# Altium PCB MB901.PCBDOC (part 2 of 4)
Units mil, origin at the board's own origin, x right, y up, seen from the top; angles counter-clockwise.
Board outline 4505 x 7005 mil, 4 copper layers (TopLayer, GND, VCC, BottomLayer); 333 components, 312 nets, 1570 pads, 794 vias.
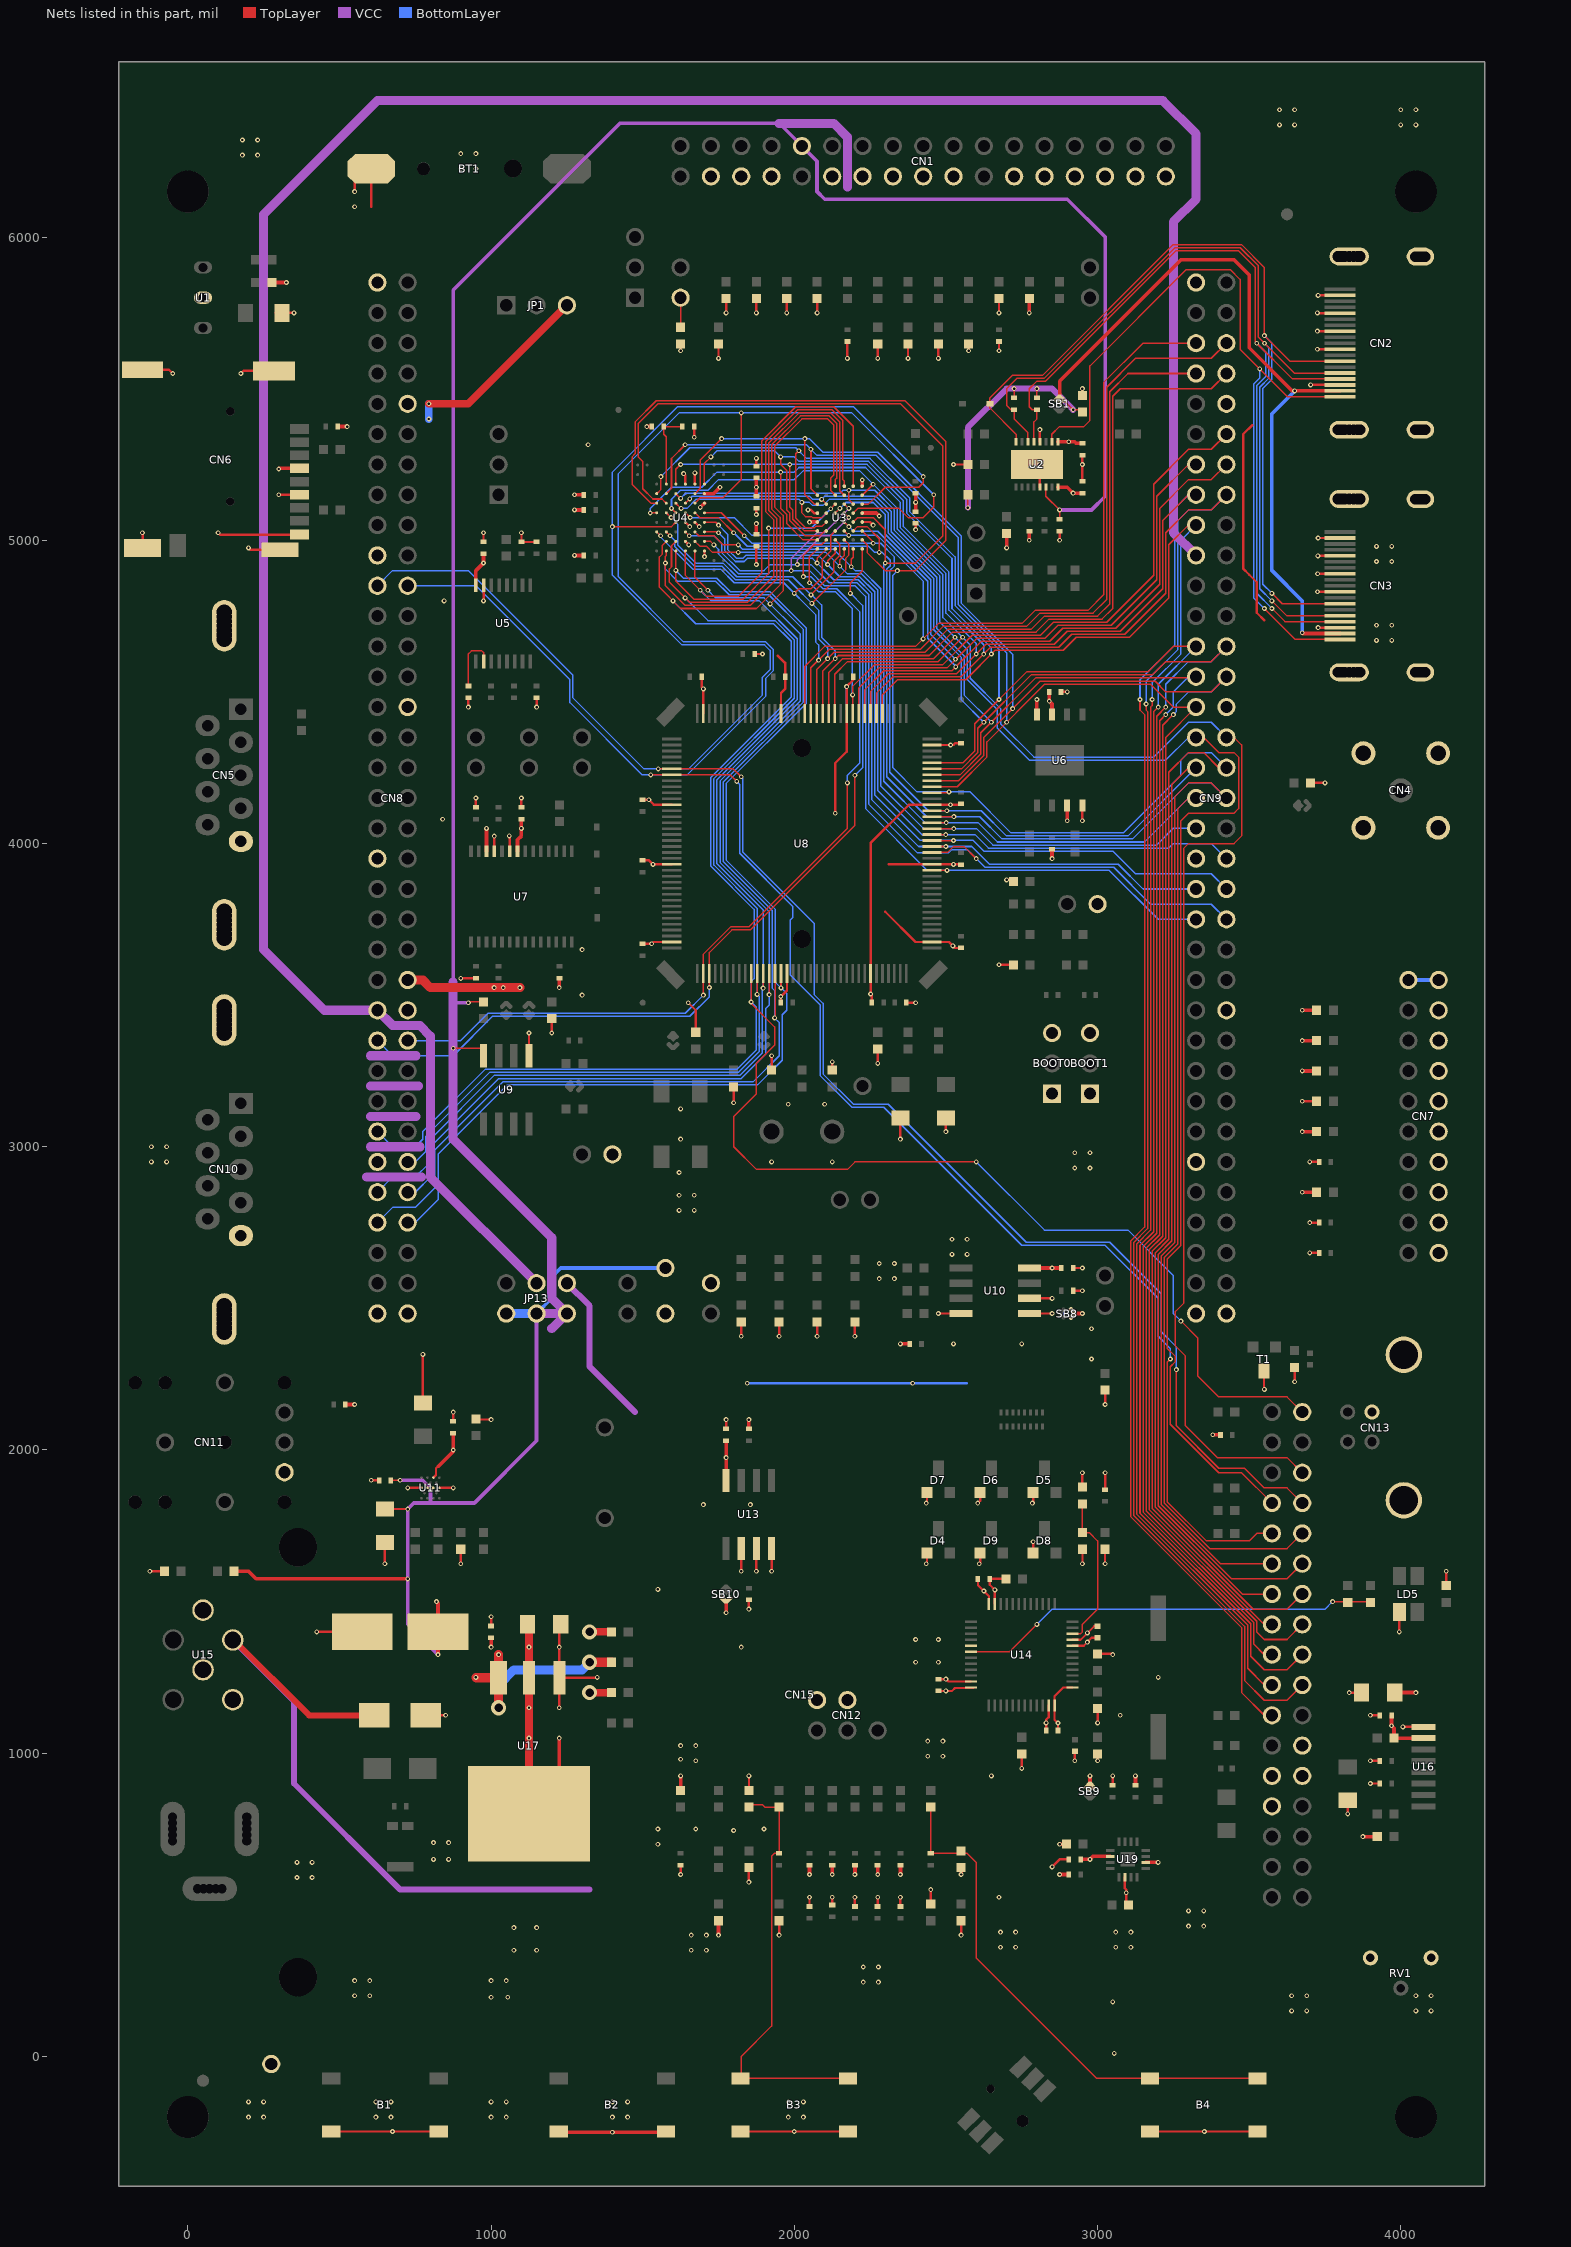
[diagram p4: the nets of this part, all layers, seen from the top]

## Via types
v1: diameter 16, hole 8, TopLayer to BottomLayer, tented both sides, 671 vias
v2: diameter 16, hole 8, TopLayer to BottomLayer, 117 vias
v3: diameter 50, hole 28, TopLayer to BottomLayer, 5 vias
v4: diameter 50, hole 28, TopLayer to BottomLayer, tented both sides, 1 vias

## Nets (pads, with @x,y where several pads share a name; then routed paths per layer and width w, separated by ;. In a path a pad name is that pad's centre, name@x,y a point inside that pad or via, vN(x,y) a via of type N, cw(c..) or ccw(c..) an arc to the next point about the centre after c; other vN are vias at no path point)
+3V3: B2.1 B2.4 BOOT0.1 BOOT1.1 C16.1 C17.2 C18.1 C19.1 C21.1 C22.2 C23.1 C31.2 C34.2 C56.2 C59.2 C61.1 C67.2 C68.2 C69.1 C70.1 C72.2 C74.1 C77.1 C78.1 C83.1 CN1.28 CN6.4 CN7.1 CN7.2 CN8.48 CN8.69 CN9.69 CN12.4 CN15.24 CN15.25 JP1.3 JP10.2 R2.2 R10.2 R15.2 R17.1 R21.2 R23.2 R25.1 R27.1 R29.1 R31.1 R32.1 R34.1 R45.2 R50.1 R54.2 R57.2 R63.2 R67.2 R69.2 R80.2 R82.1 R83.1 R84.2 R86.1 R87.2 R91.1 R96.1 R102.2 R111.2 R112.1 R114.2 R115.1 R117.2 R118.1 R119.2 R120.2 R121.2 R122.2 R123.2 R124.1 R131.2 R137.1 RV1.1 SB8.1 SB9.2 SB10.1 T1.3 TP5.1 U2.8 U2.9 U3.A6 U3.D6 U3.E1 U4.B6 U4.C6 U5.16 U6.3 U6.7 U6.8 U7.22 U7.26 U10.8 U11.E3 U13.8 U14.1 U14.9 U14.24 U14.36 U14.48 U16.7 U17.2 U19.6 U19.14 | length 6378.7
  TopLayer w7: U11.E3@809.84,1909.09 810,1909.09 818.53,1917.62 818.53,1939.53 826,1947 ; R83.1@952.5,2100 v1(1000,2100) ; v2(1100,5025) R31.1@1100,4994.5 R27.1@1150,4994.5 ; R102.2@1850,877.5 v2(1850,925) ; C74.1@2475,1205.5 2520.5,1205.5 2530,1215 U14.36@2590,1215 ; C67.2@2605.5,1575 2605.5,1554.5 2641.73,1518.27 U14.24@2641.73,1492.32 ; C68.2@2869.5,1075 v2(2869.5,1099.5) 2858.27,1110.73 2858.27,1188.27 2886.73,1216.73 U14.1@2917.32,1216.73 ; U14.9@2917.32,1374.21 2944.21,1374.21 2989,1419 C72.2@3000,1419 ; v2(2950,1625) R91.1@2950,1672.5 ; v2(3025,1625) R87.2@3025,1672.5 ; T1.3@3549.5,2260 3549.5,2200.5 v2(3550,2200) ; R131.2@4150,1552.5 v2(4150,1600)
  TopLayer w12: R2.2@277.5,5850 v1(325,5850) ; v1(300,5235) 302.01,5237.01 CN6.4@368.35,5237.01 ; R15.2@494.5,5375 v1(525,5375) ; R82.1@519.5,2150 v1(550,2150) ; 826.5,1946.5 875,1995 C61.1@875,2055.5 ; U5.16@950,4851.97 950,4900 v1(975,4925) C23.1@975,4955.5 ; U7.26@984.84,3974.61 v1(984.84,4049.84) ; v1(1000,1350) C70.1@1000,1380.5 ; U7.22@1087.2,3974.61 1087.2,4012.2 1100,4025 C34.2@1100,4080.5 ; U17.2@1225,880 v2(1225,1050) ; v1(1225,3525) R50.1@1225,3555.5 ; B2.1@1225.33,-250 B2.4@1580,-250 ; v1(1275,4950) R32.1@1305.5,4950 ; v1(1275,5100) R25.1@1305.5,5100 ; v1(1275,5150) R21.2@1305.5,5150 ; v1(1513.5,5375) R17.1@1530.5,5375 ; R111.2@1625,877.5 v1(1625,925) ; v1(1690,5108.5) U4.C6@1703.74,5122.24 ; U4.B6@1703.74,5153.74 1733.74,5153.74 v1(1755,5175) ; v1(1750,400) R124.1@1750,447.5 ; v1(1775,1463) SB10.1@1775,1500 ; U13.8@1775,1900 C59.2@1775,2030.5 ; R86.1@1850,2069.5 v1(1850,2100) ; C21.1@1875,5019.5 v1(1875,5055) ; C22.2@1875,5144.5 C17.2@1875,5205.5 ; v1(2050,600) R117.2@2050,630.5 ; v1(2050,5060) 2050.24,5060.24 U3.E1@2076.18,5060.24 ; v1(2125,600) R118.1@2125,630.5 ; v1(2200,600) R119.2@2200,630.5 ; U3.D6@2223.82,5089.76 2270.24,5089.76 v1(2280,5080) ; U3.A6@2223.82,5178.35 v2(2223.82,5198.82) ; v1(2275,600) R120.2@2275,630.5 ; v1(2350,600) R121.2@2350,630.5 ; v1(2350,2350) R80.2@2380.5,2350 ; C18.1@2400,5094.5 R23.2@2400,5155.5 ; v1(2550,600) R122.2@2550,630.5 ; v1(2700,4975) R29.1@2700,5022.5 ; U10.8@2775,2600 C56.2@2880.5,2600 ; v1(2775,5000) R34.1@2775,5030.5 ; v1(2775,5750) R10.2@2775,5797.5 ; U6.8@2800,4425 v1(2800,4475) ; C31.2@2840.5,4500 v1(2840.5,4469.5) 2850,4460 U6.7@2850,4425 ; v1(2850,3950) R45.2@2850,3980.5 ; U2.8@2868.9,5175.2 2899.8,5175.2 v1(2919.5,5155.5) C19.1@2950,5155.5 ; U2.9@2868.9,5324.8 2925,5324.8 2930.3,5319.5 C16.1@2950,5319.5 ; v1(2875,600) R123.2@2905.5,600 ; v1(2875,700) R112.1@2905.5,700 ; v1(2900,4075) U6.3@2900,4125 ; SB8.1@2920,2450 v1(2950,2450) ; C83.1@2944.5,650 v1(2975,650) 2984.84,659.84 U19.6@3041.26,659.84 ; SB9.2@2975,888 v1(2975,925) ; R114.2@3125,894.5 v1(3125,925) ; U19.14@3158.74,640.16 v1(3199.84,640.16) ; v1(3380,2050) R84.2@3405.5,2050 ; v1(3675,2850) R69.2@3722.5,2850 ; v1(3675,3050) R67.2@3722.5,3050 ; v1(3675,3250) R63.2@3722.5,3250 ; v1(3675,3350) R57.2@3722.5,3350 ; v1(3675,3450) R54.2@3722.5,3450 ; v1(3875,725) R115.1@3922.5,725 ; C78.1@3969.5,1125 v1(3969.5,1090.5) 3977.5,1082.5 R96.1@3977.5,1050 3978.09,1049.41 U16.7@4075,1049.41 ; C77.1@3980,1200 v1(4050,1200)
  TopLayer w25: v2(795,5450) 925,5450 JP1.3@1250,5775 ; U17.2@1125,795 C69.1@1125,1430 ; v3(1325,1200) R137.1@1397.5,1200
  TopLayer w30: CN8.48@725,3550 775,3550 800,3525 v1(1095,3525)
  BottomLayer w12: CN7.1@4025,3550 CN7.2@4125,3550
  BottomLayer w25: v2(795,5400) v2(795,5450)
  other v1: 1400,-250 1775,1975 875,2000 2850,2600 1010,3525 1040,3525 1100,4050 2400,5125 1875,5175 2905,5324.8
  other v2: 1125,1050 1125,1150 2500,1205.5 1125,1350 2966.64,1396.64 2625,1535
+5V: C20.1 C60.1 C62.1 C71.1 CN1.25 JP13.1 JP13.3 JP13.5 R55.2 R92.2 R136.1 TP4.1 U2.6 U9.8 U11.C3 U11.C5 U17.3 | length 11892.9
  TopLayer w5: C60.1@669.5,1900 v1(700,1900) ; U11.C5@790.16,1875 U11.C3@809.84,1875 ; v1(875,3325) U9.8@975,3325 ; v1(925,3475) 927.5,3477.5 R55.2@975,3477.5 ; U2.6@2829.53,5175.2 2829.53,5145.47 v1(2875,5100) C20.1@2875,5069.5
  TopLayer w7: C62.1@650,1805 v1(725,1805)
  TopLayer w12: R92.2@152.5,1600 200,1600 225,1575 v1(725,1575) ; v2(820,1500) 825,1495 v1(825,1325)
  TopLayer w30: v1(950,1250) 951.18,1248.82 U17.3@1025,1248.82 ; v4(1025,1150) v1(1025,1325) ; v3(1325,1300) R136.1@1397.5,1300
  VCC w12: v1(700,1900) 775,1900 v1(800,1875) 800,1825 ; v1(825,1325) 725,1425 v1(725,1805) 745,1825 945,1825 1150,2030 JP13.3@1150,2450 ; 875,3475 v1(925,3475) ; 875,3542.39 875,5825 1425,6375 1950,6375 2075,6250 2075,6150 2100,6125 2900,6125 3025,6000 3025,5145 2980,5100 v1(2875,5100)
  VCC w30: 875,3542.39 875,3025 1200,2700 1200,2500 JP13.5@1250,2450 ; JP13.3@1150,2450 JP13.5@1250,2450 ; 1200,2400 JP13.5@1250,2450 ; 1950,6375 2130,6375 2175,6330 2175,6165
  BottomLayer w12: JP13.3@1150,2450 1200,2500 1200,2570 1230,2600 TP4.1@1575,2600
  BottomLayer w30: v4@1025,1170 1025,1225 1075,1275 1300,1275 v3(1325,1300) ; JP13.1@1050,2450 JP13.3@1150,2450
A0: CN8.57 CN15.2 U3.A3 U4.G2 U8.10 | length 8019.9
  TopLayer w5: U4.G2@1577.76,4996.26 1565,4983.5 1565,4955 1555,4945 1555,4845 1625,4775 1875,4775 1952.83,4852.83 1952.83,5075.45 1925,5103.28 1925,5315 2020,5410 2115,5410 2140,5385 2140,5204.76 2135.24,5200 U3.A3@2135.24,5178.35 ; U8.10@1857.68,3570.87 1857.68,3472.32 1935,3395 1935,3335 1875,3275 1875,3175 1800,3100 1800,3000 1875,2925 2175,2925 2200,2950 v2(2600,2950) ; v1(3275,2425) 3330,2370 3330,2245 3400,2175 3625,2175 CN15.2@3675,2125
  BottomLayer w5: CN8.57@625,3050 675,3000 750,3000 775,3025 775,3050 980,3255 1810,3255 1875,3320 1875,3460 v2(1857.68,3477.32) 1857.68,3545 1867.36,3554.68 1867.36,3782.64 1725,3925 1725,4218.43 1990,4483.43 1990,4666.72 1931.72,4725 1675,4725 v1(1600,4800) ; v2(2600,2950) 2825,2725 3100,2725 3250,2575 3250,2450 v1(3275,2425)
A1: CN8.60 U3.A4 U4.G3 U8.11 | length 4891.9
  TopLayer w5: U4.G3@1609.25,4996.26 1595,4982.01 1595,4912.24 1587.76,4905 1587.76,4862.24 1655,4795 1845,4795 1932.83,4882.83 1932.83,5067.17 1905,5095 1905,5325 2010,5430 2125,5430 2160,5395 2160,5200 2164.76,5195.24 U3.A4@2164.76,5178.35 ; v1(1877.36,3502.36) U8.11@1877.36,3570.87
  BottomLayer w5: CN8.60@725,2950 750,2950 785,2985 785,3035 995,3245 1815,3245 1885,3315 1885,3494.72 v1(1877.36,3502.36) 1877.36,3786.78 1735,3929.14 1735,4214.29 2000,4479.29 2000,4670.86 1935.86,4735 1715,4735 v1(1640,4810)
A2: CN8.61 U3.A5 U4.H4 U8.12 | length 4874.8
  TopLayer w5: U4.H4@1640.75,4964.76 1640.75,4884.25 1710,4815 1815,4815 1892.5,4892.5 1892.5,5327.5 2005,5440 2130,5440 2194.29,5375.71 U3.A5@2194.29,5178.35 ; v1(1897.05,3522.95) U8.12@1897.05,3570.87
  BottomLayer w5: CN8.61@625,2850 675,2900 750,2900 795,2945 795,3020 1010,3235 1820,3235 1895,3310 v1@1895,3520.9 ; v1(1690.03,4834.97) 1725,4800 1885,4800 2010,4675 2010,4475.15 1745,4210.15 1745,3933.28 1897.05,3781.24 v1(1897.05,3522.95)
A3: CN8.62 U3.B3 U4.H5 U8.13 | length 4606.8
  TopLayer w5: U4.H5@1672.24,4964.76 1672.24,4877.76 v1(1715,4835) ; v1(1916.73,3501.73) U8.13@1916.73,3570.87 ; v1(1920,4790) 1962.83,4832.83 1962.83,5082.17 1935,5110 1935,5310 2025,5400 2110,5400 2130,5380 2130,5215 2120,5205 2120,5164.06 U3.B3@2135.24,5148.82
  BottomLayer w5: CN8.62@725,2850 750,2850 805,2905 805,3005 1025,3225 1825,3225 1905,3305 1905,3455 1916.73,3466.73 1916.73,3775.69 1755,3937.43 1755,4206 2020,4471 2020,4690 1900,4810 1740,4810 v1(1715,4835)
A4: CN8.63 U3.B4 U4.H2 U8.14 | length 5462.1
  TopLayer w5: U4.H2@1577.76,4964.76 1577.76,4950 1575,4947.24 1575,4850 1640,4785 1855,4785 1942.83,4872.83 1942.83,5071.31 1915,5099.14 1915,5320 2015,5420 2120,5420 2150,5390 2150,5163.58 U3.B4@2164.76,5148.82 ; v1@1936.42,3426.42 U8.14@1936.42,3570.87
  BottomLayer w5: CN8.63@625,2750 675,2800 750,2800 815,2865 815,2990 1040,3215 1865,3215 1950,3300 1950,3410 v1(1935,3425) 1935,3515 1926.73,3523.27 1926.73,3779.84 1765,3941.57 1765,4201.86 2030,4466.86 2030,4705.86 1915.86,4820 1785.15,4820 1740.15,4865 1615,4865 1575,4905 v1(1575,4925)
A5: CN8.64 U3.C3 U4.H3 U8.15 | length 4593
  TopLayer w5: U4.H3@1610,4964.02 U4.H3@1609.25,4964.76 1609.25,4865.75 1670,4805 1830,4805 1915,4890 v2(1915,5040) ; v1(1956.1,3523.9) U8.15@1956.1,3570.87 ; v1@2120.94,5105 U3.C3@2135.24,5119.29
  BottomLayer w5: CN8.64@725,2750 750,2750 825,2825 825,2975 1055,3205 1880,3205 1960,3285 1960,3435 1975,3450 1975,3505 1936.73,3543.27 1936.73,3783.98 1775,3945.71 1775,4197.72 2040,4462.72 2040,4710 1920,4830 1789.29,4830 1744.29,4875 1635,4875 v1(1609.25,4900.75) ; v2(1915,5040) 2055.94,5040 v1(2120,5104.06)
A6: CN9.43 U3.C4 U4.G6 U8.50 | length 2932.6
  TopLayer w5: U4.G6@1703.74,4996.26 1723.74,4996.26 v1(1735,4985) ; U3.C4@2164.76,5119.29 v1@2179.06,5105 ; U8.50@2454.13,3911.42 v1(2503.58,3911.42)
  VCC w5: v1(1990,4900) 1990,4940 2075,5025 2100,5025 v1(2180,5105)
  BottomLayer w5: v1(1735,4985) 1750,4970 1750,4955 1815,4890 1915,4890 1925,4900 2050,4900 2100,4850 2200,4850 2235,4815 2235,4115 2438.58,3911.42 3038.58,3911.42 3200,3750 CN9.43@3325,3750
A7: CN9.44 U3.D4 U4.F4 U8.53 | length 3195.1
  TopLayer w5: U4.F4@1640.75,5027.76 v1(1653.5,5015) ; U3.D4@2164.76,5089.76 v1(2179.53,5075) ; U8.53@2454.13,3970.47 2505.47,3970.47 2525,3990 2560,3990 v1(2600,3950)
  VCC w5: v1(2010,4920) 2010,4935 2090,5015 2119.53,5015 v1(2179.53,5075)
  BottomLayer w5: v1(1653.5,5015) 1735,5015 1760,4990 1760,4960 1820,4900 1900,4900 1920,4920 2055,4920 2115,4860 2206.72,4860 2245,4821.72 2245,4130 2405,3970 2510,3970 2520,3980 2570,3980 2628.58,3921.42 3053.58,3921.42 3175,3800 3375,3800 CN9.44@3425,3750
A8: CN9.41 U3.H2 U4.F6 U8.54 | length 2644.4
  TopLayer w5: U4.F6@1703.74,5027.76 1747.24,5027.76 v1(1750,5025) ; v1(2075,4925) 2075,4940.94 U3.H2@2105.71,4971.65 ; U8.54@2454.13,3990.16 v1(2500,3990.16)
  BottomLayer w5: v1(1750,5025) 1770,5005 1770,4965.86 1805.86,4930 1835,4930 1845,4940 2060,4940 2130,4870 2210.86,4870 2255,4825.86 2255,4145 2409.84,3990.16 2584.84,3990.16 2643.58,3931.42 3068.58,3931.42 3150,3850 CN9.41@3325,3850
A9: CN9.42 U3.H3 U4.E6 U8.55 | length 2785
  TopLayer w5: U4.E6@1703.74,5059.25 1740.75,5059.25 v1(1750,5050) ; v1(2110,4920) 2110,4932.22 2135.24,4957.46 U3.H3@2135.24,4971.65 ; U8.55@2454.13,4009.84 v1@2524.84,4009.84
  BottomLayer w5: v1(1750,5050) 1780,5020 1780,4970 1810,4940 1830,4940 1840,4950 2080,4950 2150,4880 2215,4880 2265,4830 2265,4160 2415,4010 2590,4010 2625,3975 3050,3975 3125,3900 3375,3900 CN9.42@3425,3850
  other v1: 2525,4010
A10: CN9.40 U3.H4 U4.G5 U8.56 | length 2694.7
  TopLayer w5: U4.G5@1672.24,4996.26 1688.5,4980 1710,4980 1730,4960 v1(1815,4960) ; v1(2150,4914.14) 2150,4935.24 2164.76,4950 U3.H4@2164.76,4971.65 ; U8.56@2454.13,4029.53 v1(2499.53,4029.53)
  BottomLayer w5: v1(1815,4960) 2104.14,4960 2174.14,4890 2220.86,4890 2275,4835.86 2275,4175 2420.47,4029.53 2595.47,4029.53 2640,3985 3235,3985 3250,4000 3375,4000 CN9.40@3425,3950
A11: CN9.37 U3.H5 U4.F5 U8.57 | length 2617.6
  TopLayer w5: U4.F5@1672.24,5027.76 1685,5015 1735,5015 1765,4985 v1(1815,4985) ; v1(2187.59,4912.59) 2187.59,4937.59 2194.29,4944.29 U3.H5@2194.29,4971.65 ; U8.57@2454.13,4049.21 v1(2525.79,4049.21)
  BottomLayer w5: v1(1815,4985) 1830,4970 2130.17,4970 2200.17,4900 2225,4900 2285,4840 2285,4190 2425.79,4049.21 2600.79,4049.21 2655,3995 3195,3995 3250,4050 CN9.37@3325,4050
A12: CN9.8 U3.G3 U4.D2 U8.87 | length 3387.7
  TopLayer w5: U4.D2@1577.76,5090.75 v1(1593.5,5075) ; v1(2055,4820) 2130,4895 2130,4930 2150,4950 2150,4986.42 U3.G3@2135.24,5001.18 ; U8.87@2093.9,4429.13 2093.9,4568.9 2145,4620 2445,4620 2522.07,4697.07 2797.07,4697.07 2840,4740 3015,4740 3050,4775 3050,5475 3075,5500 3375,5500 CN9.8@3425,5550
  BottomLayer w5: v1(1593.5,5075) 1615,5053.5 1615,4985 1675,4925 1765,4925 1810,4880 1995,4880 v1(2055,4820) 2056.87,4820 2090,4786.87 2090,4680 2135,4635 v1(2135,4610)
A13: CN9.7 U3.G4 U4.F2 U8.88 | length 3269.1
  TopLayer w5: U4.F2@1577.76,5027.76 v1@1590,5015.51 ; v1(2057.98,4792.02) 2170,4904.03 2170,4941.09 2180,4951.09 2180,4985.94 U3.G4@2164.76,5001.18 ; U8.88@2074.21,4429.13 2074.21,4574.21 2130,4630 2430,4630 2507.07,4707.07 2782.07,4707.07 2825,4750 3000,4750 3040,4790 3040,5490 3100,5550 CN9.7@3325,5550
  BottomLayer w5: v1(1590,5015) 1605,5000 1605,4980 1670,4915 1760.86,4915 1805.86,4870 1980,4870 2080,4770 2080,4675 2110,4645 v1(2110,4610)
A14: CN9.6 U3.F3 U4.F1 U8.89 | length 3452.7
  TopLayer w5: U4.F1@1546.26,5027.76 v1(1559.02,5015) ; v1(2000,4825) 2015,4840 2055,4840 2092.78,4877.78 2092.78,4937.78 2120,4965 2120,5015.47 U3.F3@2135.24,5030.71 ; U8.89@2054.53,4429.13 2054.53,4579.53 2115,4640 2415,4640 2492.07,4717.07 2767.07,4717.07 2810,4760 2985,4760 3030,4805 3030,5505 3125,5600 3375,5600 CN9.6@3425,5650
  BottomLayer w5: v1(1559.02,5015) 1559.02,5010.98 1665,4905 1756.72,4905 1801.72,4860 1965,4860 2070,4755 2070,4665 2080,4655 v1(2080,4605)
A15: CN9.5 U3.F4 U4.D4 U8.90 | length 3386.4
  TopLayer w5: U4.D4@1640.75,5090.75 v1(1656.5,5075) ; U8.90@2034.84,4429.13 2034.84,4584.84 2100,4650 2400,4650 2477.07,4727.07 2752.07,4727.07 2795,4770 2970,4770 3020,4820 3020,5520 3150,5650 CN9.5@3325,5650 ; U3.F4@2164.76,5030.71 v1(2179.53,5015.94)
  BottomLayer w5: v1(1656.5,5075) 1801.72,5075 1860.77,5015.94 2274.06,5015.94 2424.7,4865.3 v1(2424.7,4674.7) v1@2425,4675
A16: CN9.14 U3.E4 U8.80 | length 2399.9
  TopLayer w5: U3.E4@2164.76,5060.24 v1(2180,5045) ; U8.80@2231.69,4429.13 2231.69,4506.69 2295,4570 2520,4570 v1@2532.5,4582.5 ; v1(2532.38,4582.62) 2532.62,4582.62 2617.07,4667.07 2842.07,4667.07 2885,4710 3060,4710 3205,4855 3205,5105 3300,5200 3375,5200 CN9.14@3425,5250
  BottomLayer w5: v1(2180,5045) 2195,5030 2275,5030 2440,4865 2440,4677.15 v1@2532.38,4584.77
A17: CN9.13 U3.D3 U8.81 | length 2430.9
  TopLayer w5: U3.D3@2135.24,5089.76 v1(2150.47,5105) ; U8.81@2212.01,4429.13 2212.01,4512.01 2280,4580 2505,4580 v1@2532.07,4607.07 ; v1@2532.56,4607.56 2602.07,4677.07 2827.07,4677.07 2870,4720 3045,4720 3195,4870 3195,5145 3300,5250 CN9.13@3325,5250
  BottomLayer w5: v1(2150.47,5105) 2170.03,5124.56 2260.44,5124.56 2300,5085 2300,5020 2450,4870 2450,4689.14 v1(2531.58,4607.56)
A18: CN9.12 U3.H1 U8.82 | length 2424
  TopLayer w5: v1(2050,4860) 2050,4945.47 U3.H1@2076.18,4971.65 ; U8.82@2192.32,4429.13 2192.32,4517.32 2265,4590 2490,4590 2587.07,4687.07 2812.07,4687.07 2855,4730 3030,4730 3185,4885 3185,5185 3300,5300 3375,5300 CN9.12@3425,5350
  BottomLayer w5: v1(2050,4860) 2080,4830 2135.86,4830 2191.17,4774.69 v1@2191.17,4491.16
  other v1: 2192.32,4490
A19: CN8.52 U3.G2 U8.2 | length 2950.1
  TopLayer w5: v1(1700.2,3500.2) 1700.2,3635.2 1790,3725 1850,3725 2175,4050 v1(2175,4200) ; v1(2030,4880) 2030,4950 2066,4986 2090.53,4986 U3.G2@2105.71,5001.18
  BottomLayer w5: CN8.52@725,3350 900,3350 990,3440 1640,3440 v1(1700.2,3500.2) ; v1(2030,4880) 2055,4880 2095,4840 2140,4840 2215,4765 2215,4265 2175,4225 v1(2175,4200)
A20: CN8.51 U3.H6 U8.3 | length 2950.6
  TopLayer w5: v1(1719.88,3525.12) 1719.88,3640.74 1794.14,3715 1855,3715 2200,4060 v1(2200,4225) ; v1(2185,4825) 2185,4860 2223.82,4898.82 U3.H6@2223.82,4971.65
  BottomLayer w5: CN8.51@625,3350 675,3300 875,3300 1005,3430 1655,3430 1719.88,3494.88 v1(1719.88,3525.12) ; v1(2185,4825) 2225,4785 2225,4250 v1(2200,4225)
AIN_1: R91.2 R93.1 U14.10 | length 512.3
  TopLayer w5: U14.10@2917.32,1393.9 2943.9,1393.9 2950,1400 2950,1425 3000,1475 3000,1700 2972.5,1727.5 R91.2@2950,1727.5 R93.1@2950,1822.5
D0: CN9.32 CN15.6 U3.B6 U4.D3 U8.85 | length 6194.9
  TopLayer w5: v1(1595,5105) U4.D3@1609.25,5090.75 ; U8.85@2133.27,4429.13 2133.27,4558.27 2175,4600 2475,4600 v1(2555,4680) ; U3.B6@2223.82,5148.82 v1(2260,5185) ; CN9.32@3425,4350 3450,4350 3475,4325 3475,4025 3450,4000 3300,4000 3285,3985 3285,2485 3257.01,2457.01 3257.01,2342.99 3290,2310 3290,2080 3395,1975 3625,1975 CN15.6@3675,1925
  BottomLayer w5: v1(1595,5105) 1595,5135 1625,5165 1715,5165 1750,5200 2000,5200 2030,5230 2215,5230 2340,5105 2340,5036.57 2490,4886.57 2490,4745 2580,4655 2580,4545 2680,4445 2680,4395 2790,4285 3185,4285 3300,4400 3375,4400 CN9.32@3425,4350
D1: CN9.31 CN15.7 U3.C5 U4.B3 U8.86 | length 6019.6
  TopLayer w5: U4.B3@1609.25,5153.74 v1(1625,5137.99) ; U8.86@2113.58,4429.13 2113.58,4563.58 2160,4610 2460,4610 v1(2530,4680) ; v1(2180,5165) 2180,5133.58 U3.C5@2194.29,5119.29 ; CN9.31@3325,4350 3350,4350 3400,4300 3450,4300 3465,4285 3465,4115 3450,4100 3300,4100 3275,4075 3275,2675 3230,2630 3230,2335 3257.01,2307.99 3257.01,2291.5 3240,2274.49 3240,2085 3400,1925 3475,1925 CN15.7@3575,1825
  BottomLayer w5: v1(1625,5137.99) 1642.01,5155 2150.44,5155 2160.44,5165 2265,5165 2330,5100 2330,5032.43 2480,4882.43 2480,4730 2570,4640 2570,4540.86 2670,4440.86 2670,4380 2775,4275 3225,4275 3300,4350 CN9.31@3325,4350
D2: CN8.21 CN15.8 U3.C6 U4.E3 U8.114 | length 8269.6
  TopLayer w5: v1(1400,5045) 1595,5045 U4.E3@1609.25,5059.25 ; v1(1551.06,4246.06) 1798.94,4246.06 v1(1825,4220) ; U3.C6@2223.82,5119.29 2244.29,5119.29 2300,5175 2410,5175 2425,5190 v1(2425,5210) ; v1(3260,2265) 3260,2080 3400,1940 3485,1940 3550,1875 3625,1875 CN15.8@3675,1825
  BottomLayer w5: CN8.21@625,4850 675,4900 925,4900 1270,4555 1270,4480 1503.94,4246.06 1651.06,4246.06 1895,4490 1895,4548.28 1920,4573.28 1920,4636.72 1901.72,4655 1630,4655 1400,4885 1400,5225 1615,5440 2195,5440 v1(2425,5210) ; v1(1825,4220) 1830,4215 1830,3971.72 2065,3736.72 2065,3502.43 2095,3472.43 2095,3240 2195,3140 2310,3140 2765,2685 3040,2685 3210,2515 3210,2390 3260,2340 v1(3260,2265)
D3: CN8.22 CN15.9 U3.D5 U4.C5 U8.115 | length 8587
  TopLayer w5: v1(1526.38,4226.38) 1788.62,4226.38 v1(1810,4205) ; U4.C5@1672.24,5122.24 1690,5140 1765,5140 1825,5200 v1(1825,5420) ; U3.D5@2194.29,5089.76 2209.53,5105 2345,5105 2375,5075 2425,5075 2460,5110 v1(2460,5150) ; v1(3240,2300) 3230,2290 3230,1828.85 3358.85,1700 3500,1700 3525,1725 CN15.9@3575,1725
  BottomLayer w5: CN8.22@725,4850 950,4850 1260,4540 1260,4465 1498.62,4226.38 1646.38,4226.38 1905,4485 1905,4544.14 1930,4569.14 1930,4640.86 1905.86,4665 1635,4665 1420,4880 1420,5220 1620,5420 2190,5420 v1(2460,5150) ; v1(1810,4205) 1820,4195 1820,3967.57 1995,3792.57 1995,3755.86 1986.1,3746.96 1986.1,3567.18 2085,3468.28 2085,3235 2190,3130 2295,3130 2750,2675 3025,2675 3200,2500 3200,2375 3240,2335 v1(3240,2300)
D4: CN9.35 CN15.10 U3.E5 U4.C2 U8.58 | length 7032.4
  TopLayer w5: U4.C2@1577.76,5122.24 1563.87,5136.13 1533.87,5136.13 1500,5170 1500,5260 1485,5275 1485,5385 1550,5450 2350,5450 2490,5310 2490,5015 2400,4925 v1(2300,4925) 2300,5035 2260,5075 2209.06,5075 U3.E5@2194.29,5060.24 ; U8.58@2454.13,4068.9 v1(2501.1,4068.9) ; CN9.35@3325,4150 3300,4150 3265,4115 3265,2680 3220,2635 3220,1824.71 3369.71,1675 3625,1675 CN15.10@3675,1725
  BottomLayer w5: v1(2300,4925) 2295,4920 2295,4205 2431.1,4068.9 2606.1,4068.9 2670,4005 3155,4005 3300,4150 CN9.35@3325,4150
D5: CN9.36 CN15.11 U3.F5 U4.D5 U8.59 | length 5963.6
  TopLayer w5: U4.D5@1672.24,5090.75 1687.99,5075 1750,5075 v1(1800,5025) ; U3.F5@2194.29,5030.71 2208.58,5045 2240,5045 2280,5005 v1(2280,4960) ; U8.59@2454.13,4088.58 v1(2526.42,4088.58) ; CN9.36@3425,4150 3375,4200 3300,4200 3255,4155 3255,2685 3210,2640 3210,1820.56 3405.56,1625 CN15.11@3575,1625
  BottomLayer w5: v1(1800,5025) 1845,4980 2245,4980 2265,4960 2290,4960 2316.18,4933.82 2316.18,4916.18 2305,4905 2305,4220 2436.42,4088.58 2611.42,4088.58 2685,4015 3115,4015 3300,4200 3375,4200 CN9.36@3425,4150
D5V: CN8.49 CN9.19 JP13.4 | length 9582.9
  VCC w30: 590,2900 770,2900 ; 602.09,3000 765,3000 ; 602.09,3100 752.43,3100 ; 602.09,3200 760,3200 ; 602.09,3300 752.75,3300 ; JP13.4@1150,2550 800,2900 800,3365 765,3400 675,3400 CN8.49@625,3450 450,3450 250,3650 250,6075 625,6450 3215,6450 3325,6340 3325,6125 3250,6050 3250,5025 CN9.19@3325,4950
D6: CN9.33 CN15.12 U3.F6 U4.D6 U8.60 | length 5793.6
  TopLayer w5: U4.D6@1703.74,5090.75 1759.25,5090.75 v1(1835,5015) ; U3.F6@2223.82,5030.71 2260,4994.53 v1(2260,4990) ; U8.60@2454.13,4108.27 v1(2503.27,4108.27) ; CN9.33@3325,4250 3300,4250 3245,4195 3245,2690 3200,2645 3200,1816.42 3441.42,1575 3625,1575 CN15.12@3675,1625
  BottomLayer w5: v1(1835,5015) 1860,4990 2285,4990 2330,4945 2330,4915 2315,4900 2315,4235 2441.73,4108.27 2616.73,4108.27 2700,4025 3100,4025 CN9.33@3325,4250
D7: CN9.34 CN15.13 U3.G6 U4.C1 U8.63 | length 7370.5
  TopLayer w5: U4.C1@1546.26,5122.24 1527.76,5122.24 1465,5185 1465,5275 1475,5285 1475,5390 1545,5460 2365,5460 2500,5325 2500,5000 2400,4900 2300,4900 2240,4960 2240,4985 U3.G6@2223.82,5001.18 ; U8.63@2454.13,4167.32 2507.32,4167.32 v1(2510,4170) ; CN9.34@3425,4250 3400,4250 3350,4300 3300,4300 3235,4235 3235,2695 3190,2650 3190,1812.28 3477.28,1525 CN15.13@3575,1525
  BottomLayer w5: v1(2340,4900) 2325,4885 2325,4250 2405,4170 2580,4170 2715,4035 3085,4035 3275,4225 3275,4275 3300,4300 3375,4300 CN9.34@3425,4250
D8: CN9.29 CN15.14 U3.B1 U4.B2 U8.64 | length 6451.5
  TopLayer w5: U4.B2@1577.76,5153.74 1595,5170.98 1595,5270 v1(1640,5315) ; v1@2055,5300 2055,5170 U3.B1@2076.18,5148.82 ; U8.64@2454.13,4187.01 2537.01,4187.01 2635,4285 2635,4335 2825,4525 3175,4525 3250,4450 CN9.29@3300,4450 ; CN9.29@3325,4450 3225,4350 3225,2700 3180,2655 3180,1808.14 3513.14,1475 3625,1475 CN15.14@3675,1525
  BottomLayer w5: v1(1640,5315) 2040,5315 2075,5280 2270,5280 2540,5010 2540,4789.14 2700,4629.14 v1(2700,4400)
  other v1: 2054.83,5300.17
D9: CN9.28 CN15.15 U3.C1 U4.B5 U8.65 | length 6654.4
  TopLayer w5: U4.B5@1672.24,5153.74 1690,5171.5 1690,5265 v1(1760.11,5335.11) ; v1(2035,5335.11) 2035,5150 2065.71,5119.29 U3.C1@2076.18,5119.29 ; U8.65@2454.13,4206.69 2541.69,4206.69 2625,4290 2625,4350 2810,4535 3190,4535 3225,4500 3375,4500 CN9.28@3425,4550 ; v1(3250,4425) 3215,4390 3215,2705 3170,2660 3170,1804 3549,1425 CN15.15@3575,1425
  BottomLayer w5: v1(1760.11,5335.11) 2049.89,5335.11 2095,5290 2275,5290 2550,5015 2550,4793.28 2720,4623.28 v1(2720,4445) ; v1(3250,4425) 3260,4435 3260,4460 3300,4500 3375,4500 CN9.28@3425,4550
D10: CN9.27 CN15.16 U3.C2 U4.C4 U8.66 | length 6189.1
  TopLayer w5: U4.C4@1640.75,5122.24 v1(1655,5136.5) ; v1(2090,5135) U3.C2@2105.71,5119.29 ; U8.66@2454.13,4226.38 2546.38,4226.38 2615,4295 2615,4365 2797.07,4547.07 CN9.27@3332.93,4547.07 ; v1(3225,4425) 3205,4405 3205,2710 3160,2665 3160,1799.85 3525,1434.85 3525,1400 3550,1375 3625,1375 CN15.16@3675,1425
  BottomLayer w5: v1(1655,5136.5) 1663.5,5145 2050,5145 2060,5135 v1(2090,5135) 2099.56,5144.56 2270.44,5144.56 2320,5095 2320,5028.28 2470,4878.28 2470,4709.14 2560,4619.14 2560,4490 v1(2650,4400) ; v1(3225,4425) 3250,4450 3250,4500 3300,4550 CN9.27@3325,4550
D11: CN9.26 CN15.17 U3.D2 U4.C3 U8.67 | length 6562.2
  TopLayer w5: U4.C3@1609.25,5122.24 v1(1626.5,5105) ; v1(2025,5125) 2025,5090 2036.74,5078.26 2056.74,5078.26 2060,5075 2090.94,5075 U3.D2@2105.71,5089.76 ; U8.67@2454.13,4246.06 2551.06,4246.06 2605,4300 2605,4380 2782.07,4557.07 3182.07,4557.07 3225,4600 3375,4600 CN9.26@3425,4650 ; v1(3225,4450) 3195,4420 3195,2715 3150,2670 3150,1795.71 3515,1430.71 3515,1360 3550,1325 CN15.17@3575,1325
  BottomLayer w5: v1(1626.5,5105) 1645.86,5105 1675.86,5135 2015,5135 v1(2025,5125) 2050,5125 2060,5115 2095,5115 2114.56,5134.56 2265.44,5134.56 2310,5090 2310,5024.14 2460,4874.14 2460,4705 2550,4615 2550,4475 v1(2625,4400) ; v1(3225,4450) 3225,4525 3300,4600 3375,4600 CN9.26@3425,4650
D12: CN9.25 CN15.18 U3.E2 U4.B1 U8.68 | length 6974.9
  TopLayer w5: U4.B1@1546.26,5153.74 1560,5167.48 v1(1560,5210) ; v1(2015,5295) 2005,5285 2005,5073.28 2037.58,5040.71 2065.71,5040.71 2071.74,5046.74 2092.21,5046.74 U3.E2@2105.71,5060.24 ; U8.68@2454.13,4265.75 2555.75,4265.75 2595,4305 2595,4395 2767.07,4567.07 3167.07,4567.07 3250,4650 CN9.25@3325,4650 ; v1(3200,4450) 3185,4435 3185,2720 3140,2675 3140,1791.57 3505,1426.57 3505,1320 3550,1275 3625,1275 CN15.18@3675,1325
  BottomLayer w5: v1(1560,5210) 1655,5305 2005,5305 2040,5270 2250,5270 2380,5140 2380,5095 2530,4945 2530,4785 2675,4640 v1(2675,4475) ; v1(3200,4450) 3200,4525 CN9.25@3325,4650
D13: CN9.17 CN15.19 U3.F2 U4.A6 U8.77 | length 7349.2
  TopLayer w5: U4.A6@1703.74,5185.24 1703.74,5253.74 v1(1725,5275) ; v1(1955,5275) 1955,5250 1975,5230 1975,5100 1985,5090 1985,5065 2035,5015 2085,5015 2100.71,5030.71 U3.F2@2105.71,5030.71 ; U8.77@2290.75,4429.13 2290.75,4490.75 2340,4540 2565,4540 2662.07,4637.07 2887.07,4637.07 2930,4680 3105,4680 3235,4810 3235,4985 3300,5050 CN9.17@3325,5050 ; v1(3180,4475) 3180,4455 3175,4450 3175,2725 3130,2680 3130,1787.43 3495,1422.43 3495,1280 3550,1225 CN15.19@3575,1225
  BottomLayer w5: v1(1725,5275) 1745,5295 1935,5295 v1(1955,5275) 2000,5275 2015,5260 2245,5260 2370,5135 2370,5090 2520,4940 2520,4775 2650,4645 v1(2650,4625) ; v1(3180,4475) 3180,4530 3275,4625 3275,5000 CN9.17@3325,5050
D14: CN9.16 CN15.20 U3.F1 U4.A3 U8.78 | length 7835.1
  TopLayer w5: U4.A3@1609.25,5185.24 1609.25,5234.25 v1(1625,5250) ; v1(1985,5250) 1985,5110 1995,5100 1995,5069.14 2033.43,5030.71 U3.F1@2076.18,5030.71 ; U8.78@2271.06,4429.13 2271.06,4496.06 2325,4550 2550,4550 2647.07,4647.07 2872.07,4647.07 2915,4690 3090,4690 3225,4825 3225,5025 3300,5100 3375,5100 CN9.16@3425,5150 ; v1(3160,4460) 3160,4440 3165,4435 3165,2730 3120,2685 3120,1783.28 3485,1418.28 3485,1240 3550,1175 3625,1175 CN15.20@3675,1225
  BottomLayer w5: v1(1625,5250) 2240,5250 2360,5130 2360,5045 2510,4895 2510,4770 2624.77,4655.23 v1(2624.77,4624.77) ; v1(3160,4460) 3160,4535 3265,4640 3265,5065 3300,5100 3375,5100 CN9.16@3425,5150
D15: CN9.15 CN15.21 U3.G1 U4.D1 U8.79 | length 7740.2
  TopLayer w5: v1(1525,5090) 1545.51,5090 U4.D1@1546.26,5090.75 ; v1(1955,5225) 1955,5105 1975,5085 1975,5055 2028.82,5001.18 U3.G1@2076.18,5001.18 ; U8.79@2251.38,4429.13 2251.38,4501.38 2310,4560 2535,4560 2632.07,4657.07 2857.07,4657.07 2900,4700 3075,4700 3215,4840 3215,5065 CN9.15@3300,5150 ; v1(3140,4475) 3140,4440 3155,4425 3155,2735 3110,2690 3110,1779.14 3475,1414.14 3475,1200 3550,1125 CN15.21@3575,1125
  BottomLayer w5: v1(1525,5090) 1525,5105 1595,5175 1695,5175 1745,5225 2000,5225 2015,5240 2235,5240 2350,5125 2350,5040.71 2500,4890.71 2500,4760 2600,4660 v1(2600,4625) ; v1(3140,4475) 3140,4540 3255,4655 3255,5105 3300,5150 CN9.15@3325,5150
E5V: C76.1 JP13.6 U15.3 | length 2769.6
  TopLayer w20: U15.3@148.43,1373.43 151.57,1373.43 400,1125 C76.1@620,1125
  VCC w20: U15.3@148.43,1373.43 350,1171.85 350,900 700,550 1325,550 ; JP13.6@1250,2550 1325,2475 1325,2275 1475,2125
GND: B1.1 B1.4 B3.1 B3.4 B4.1 B4.4 BOOT0.3 BOOT1.3 BT1.2 C1.1 C2.2 C3.1 C4.1 C5.1 C6.1 C7.1 C8.1 C9.1 C10.1 C11.1 C12.1 C13.1 C14.1 C15.2 C16.2 C17.1 C18.2 C19.2 C20.2 C21.2 C22.1 C23.2 C24.1 C27.1 C28.2 C29.2 C30.2 C31.1 C32.2 C34.1 C35.2 C36.2 C37.2 C38.2 C39.2 C40.1 C41.2 C43.2 C44.2 C45.1 C46.1 C47.2 C48.2 C50.2 C51.2 C52.2 C53.2 C54.2 C55.2 C56.1 C57.1 C58.2 C59.1 C60.2 C61.2 C62.2 C65.2 C67.1 C68.1 C69.2 C70.2 C71.2 C72.1 C73.1 C74.2 C75.1 C76.2 C77.2 C78.2 C79.1 C80.2 C82.2 C83.2 C84.1 C88.1 C89.1 C90.1 C91.1 C92.1 CN1.2 CN1.4 CN1.6 CN1.8 CN1.10 CN1.12 CN1.16 CN1.18 CN1.20 CN1.22 CN1.24 CN1.30 CN1.32 CN2.0 CN2.2 CN2.5 CN2.8 CN2.11 CN2.17 CN3.0 CN3.2 CN3.5 CN3.8 CN3.11 CN3.17 CN4.1 CN4.2 CN4.3 CN4.4 CN5.0 CN5.5 CN6.6 CN6.9 CN6.G1 CN6.G2 CN6.G3 CN6.G4 CN7.4 CN7.6 CN7.8 CN7.10 CN7.12 CN7.14 CN7.16 CN7.18 CN7.20 CN8.1 CN8.10 CN8.19 CN8.30 CN8.39 CN8.50 CN8.59 CN8.70 CN9.1 CN9.10 CN9.30 CN9.39 CN9.50 CN9.59 CN9.70 CN10.0 CN10.5 CN11.4 CN12.2 CN13.0 CN13.4 CN15.26 CN15.27 D4.2 D5.2 D6.2 D7.2 D8.2 D9.2 JP14.2 L2.1 LD1.2 LD2.2 LD3.2 LD4.2 LD5.1 LD6.2 R9.1 R19.2 R40.1 R42.2 R56.2 R61.2 R65.1 R68.1 R70.1 R71.1 R79.2 R81.1 R88.2 R93.2 R94.1 R97.1 R100.2 R113.2 R116.2 R125.1 R126.2 R127.1 R128.1 R129.1 R132.2 RV1.3 TP2.1 TP7.1 U1.2 U2.5 U2.12 U3.D1 U3.E6 U4.A4 U4.A5 U4.E4 U4.E5 U4.G4 U4.H6 U5.15 U6.4 U7.23 U7.25 U8.16 U8.30 U8.38 U8.51 U8.61 U8.71 U8.83 U8.94 U8.107 U8.120 U8.130 U8.143 U9.5 U10.4 U10.5 U10.6 U11.C1 U11.C7 U13.2 U13.3 U13.4 U14.8 U14.23 U14.35 U14.47 U15.4 U15.5 U15.6 U16.8 U17.1 U19.10 | length 13430.8
  TopLayer w8: v1(-150,5025) -149.37,5024.37 CN6.G2@-149.37,4974.21 ; CN6.G3@-149.37,5562.79 -62.79,5562.79 v1(-50,5550) ; v1(-125,1600) LD6.2@-77.5,1600 ; v2(100,5025) 106.5,5018.5 CN6.9@368.35,5018.5 ; v1(175,5550) 183.86,5558.86 CN6.G1@283.7,5558.86 ; v1(200,4975) 206.69,4968.31 CN6.G4@303.39,4968.31 ; C2.2@290,5750 v1(350,5750) ; v1(300,5150) 300.39,5150.39 CN6.6@368.35,5150.39 ; v1(425,1400) C71.2@575,1400 ; B1.1@472.83,-247.5 B1.4@827.17,-247.5 ; v1(550,6150) BT1.2@550,6220 ; v1(605,1900) C60.2@630.5,1900 ; 605,6100 BT1.2@605,6225 ; v1(650,1625) C62.2@650,1695 ; v1(725,1875) U11.C7@770.47,1875 ; C58.2@775,2155 v1(775,2315) ; C76.2@780,1125 v1(850,1125) ; U11.C1@829.53,1875 v1(875,1875) ; C61.2@875,2094.5 v1(875,2125) ; v1(900,1625) C65.2@900,1672.5 ; v1(900,3555) 900.5,3555.5 C41.2@950,3555.5 ; v1(925,4450) C24.1@925,4480.5 ; C37.2@950,4119.5 v1(950,4150) ; v1(975,4800) 975.59,4800.59 U5.15@975.59,4851.97 ; C23.2@975,4994.5 v1(975,5025) ; C70.2@1000,1419.5 v1(1000,1450) ; U7.25@1010.43,3974.61 v1(1010.43,4024.57) ; v1(1060,4025) 1061.61,4023.39 U7.23@1061.61,3974.61 ; C34.1@1100,4119.5 v1(1100,4150) ; U9.5@1125,3300 v1(1125,3375) ; v1(1150,4450) C27.1@1150,4480.5 ; v1(1200,3375) R56.2@1200,3422.5 ; v2(1225,1150) C69.2@1225,1420 ; U17.1@1225,1248.82 1348.82,1248.82 v2(1350,1250) ; C43.2@1500,3669.5 v1(1529.5,3669.5) 1535.2,3675.2 U8.143@1595.87,3675.2 ; C38.2@1500,3944.5 1520.5,3944.5 v1(1533.9,3931.1) U8.130@1595.87,3931.1 ; C35.2@1500,4144.5 v1(1520.5,4144.5) 1537.05,4127.95 U8.120@1595.87,4127.95 ; v1(1625,600) C84.1@1625,630.5 ; v1(1625,5625) C3.1@1625,5655.5 ; v1(1635,5220) 1640.75,5214.25 U4.A4@1640.75,5185.24 U4.A4@1640,5185.98 ; U4.G4@1640.75,4996.26 v1(1652.01,4985) ; U4.E4@1640.75,5059.25 v1(1655,5045) ; v1(1650,3475) 1675,3450 C50.2@1675,3377.5 ; C14.1@1669.5,5375 1669.5,5340.5 v1(1670,5340) ; U4.E5@1672.24,5059.25 v1(1686.5,5045) ; U4.A5@1672.24,5185.24 v1(1672.24,5222.24) ; C28.2@1694.5,4550 1694.5,4515.5 v1(1700.2,4509.8) U8.107@1700.2,4429.13 ; v1(1703.74,4946.26) U4.H6@1703.74,4964.76 ; v1(1750,5600) C13.1@1750,5647.5 ; C59.1@1775,2069.5 v1(1775,2100) ; v1(1775,5750) C5.1@1775,5797.5 ; v1(1800,3145) C51.2@1800,3197.5 ; B3.1@1822.83,-247.5 B3.4@2177.17,-247.5 ; v1(1825,1600) U13.2@1825,1675 ; v1(1825,2375) LD4.2@1825,2422.5 ; v1(1850,575) R116.2@1850,622.5 ; v1(1850,1475) R94.1@1850,1505.5 ; R40.1@1869.5,4625 v1(1895,4625) ; v1(1875,1600) U13.3@1875,1675 ; v1(1875,4920) C21.2@1875,4980.5 ; v1(1875,5085) C22.1@1875,5105 ; C17.1@1875,5244.5 v1(1875,5270) ; v1(1875,5750) C4.1@1875,5797.5 ; v1(1925,1600) U13.4@1925,1675 ; C52.2@1925,3252.5 v1(1925,3300) ; 1945,4620 1969.5,4595.5 1969.5,4509.5 1956.1,4496.1 U8.94@1956.1,4429.13 ; v1(1950,400) R125.1@1950,447.5 ; v1(1950,2375) LD3.2@1950,2422.5 ; C48.2@1955.5,3475 v1(1955.5,3495.5) 1975.79,3515.79 U8.16@1975.79,3570.87 ; v1(1975,5750) C6.1@1975,5797.5 ; v1(2045.17,5100) 2054.76,5100 2065,5089.76 U3.D1@2076.18,5089.76 ; C88.1@2050,494.5 v1(2050,525) ; v1(2075,2375) LD2.2@2075,2422.5 ; v1(2075,5750) C1.1@2075,5797.5 ; C89.1@2125,499.5 v1(2125,525) ; C53.2@2125,3252.5 v1(2125,3280) ; v1(2135,4100) 2135,4265 2172.64,4302.64 v1(2172.64,4517.64) 2194.5,4539.5 C30.2@2194.5,4550 ; v1(2175,5600) C7.1@2175,5655.5 ; C90.1@2200,494.5 v1(2200,525) ; v1(2200,2375) LD1.2@2200,2422.5 ; U3.E6@2223.82,5060.24 2249.76,5060.24 v1(2260,5050) ; C47.2@2255.5,3475 2255.5,3499.5 v1(2251.38,3503.62) 2251.38,4001.38 2377.95,4127.95 C36.2@2547.45,4127.95 ; C91.1@2275,494.5 v1(2275,525) ; v1(2275,3275) R61.2@2275,3322.5 ; v1(2275,5600) C8.1@2275,5647.5 ; 2300,3775 2399.8,3675.2 2509.8,3675.2 2529.5,3655.5 C44.2@2550,3655.5 ; 2311.1,3931.1 C39.2@2549.4,3931.1 ; C92.1@2350,494.5 v1(2350,525) ; v1(2350,3025) C55.2@2350,3095 ; C46.1@2369.5,3475 v1(2400,3475) ; v1(2375,5600) C9.1@2375,5647.5 ; v1(2400,5035) C18.2@2400,5055.5 ; v1(2435,1625) 2437.5,1627.5 D4.2@2437.5,1660 ; v1(2435,1825) 2437.5,1827.5 D7.2@2437.5,1860 ; R127.1@2450,502.5 v1(2450,550) ; U8.71@2454.13,4324.8 2524.8,4324.8 2530.5,4330.5 C32.2@2550,4330.5 ; C74.2@2475,1244.5 v2(2500,1244.5) 2508.08,1236.42 U14.35@2582.68,1236.42 ; v1(2475,2450) U10.4@2550,2450 ; v1(2475,5600) C10.1@2475,5647.5 ; v1(2500,3050) C54.2@2500,3095 ; v1(2525,5250) R19.2@2572.5,5250 ; v1(2550,400) R128.1@2550,447.5 ; v1(2575,5625) R9.1@2575,5655.5 ; v1(2605,1825) 2612.5,1832.5 D6.2@2612.5,1860 ; v1(2610,1625) 2612.5,1627.5 D9.2@2612.5,1660 ; U14.23@2661.42,1492.32 v2(2661.42,1538.58) 2644.5,1555.5 C67.1@2644.5,1575 R88.2@2697.5,1575 ; v1(2675,3600) C45.1@2722.5,3600 ; v1(2675,5625) C12.1@2675,5655.5 ; v1(2675,5750) C11.1@2675,5797.5 ; v1(2700,3880) C40.1@2730.5,3880 ; v2(2750,950) R81.1@2750,997.5 ; U10.5@2775,2450 v1(2850,2450) ; U10.6@2775,2500 v1(2850,2500) ; v1(2785,1825) 2787.5,1827.5 D5.2@2787.5,1860 ; D8.2@2787.5,1660 v2(2787.5,1697.5) ; U2.5@2809.84,5175.2 2809.84,5249.84 v1(2810,5250) ; U2.12@2809.84,5324.8 2809.84,5364.84 v1(2810,5365) ; C68.1@2830.5,1075 2830.5,1110.5 2838.58,1118.58 U14.47@2838.58,1157.68 ; v2(2850,625) 2875,650 C83.2@2905.5,650 ; v1(2875,5000) C20.2@2875,5030.5 ; C31.1@2879.5,4500 v1(2900,4500) ; U14.8@2917.32,1354.53 2954.53,1354.53 2981,1381 C72.1@3000,1381 ; R79.2@2919.5,2525 v1(2950,2525) ; C56.1@2919.5,2600 v1(2950,2600) ; v2(2925,975) R129.1@2925,1006 ; R93.2@2950,1877.5 v2(2950,1925) ; v1(2950,4075) U6.4@2950,4125 ; C19.2@2950,5194.5 C16.2@2950,5280.5 ; C15.2@2950,5469.5 v1(2950,5500) ; v2(3000,975) R97.1@3000,997.5 ; v2(3000,1100) C79.1@3000,1147.5 ; C75.1@3000,1327.5 3047.5,1327.5 v2(3050,1325) ; C73.1@3025,1869.5 v2(3025,1925) ; v1(3025,2150) C57.1@3025,2197.5 ; R113.2@3050,894.5 v1(3050,925) ; U19.10@3090.16,591.26 3090.16,554.84 3094.5,550.5 R126.2@3094.5,500 ; B4.1@3172.83,-247.5 B4.4@3537.5,-247.5 ; 3510.45,5380 3480,5349.55 3480,4906.71 3500.38,4886.33 3525,4861.71 3525,4761.11 3550.61,4735.5 ; v2(3650,2225) R132.2@3650,2272.5 ; v1(3675,3150) R65.1@3722.5,3150 ; v1(3700,2650) R71.1@3730.5,2650 ; v1(3700,2750) R70.1@3730.5,2750 ; v1(3700,2950) R68.1@3730.5,2950 ; R42.2@3702.5,4200 v1(3750,4200) ; v1(3702.8,5512.2) CN2.17@3800,5512.2 ; v1(3725,5630) 3725.32,5630.32 CN2.11@3800,5630.32 ; v1(3725,5690) 3725.63,5689.37 CN2.8@3800,5689.37 ; v1(3725,5750) 3726.57,5748.43 CN2.5@3800,5748.43 ; v1(3725.32,4830.32) CN3.11@3800,4830.32 ; v1(3725.63,4889.37) CN3.8@3800,4889.37 ; v1(3726.57,4948.43) CN3.5@3800,4948.43 ; v1(3727.2,4712.2) CN3.17@3800,4712.2 ; v1(3727.48,5007.48) CN3.2@3800,5007.48 ; v1(3727.48,5807.48) CN2.2@3800,5807.48 ; v1(3825,800) C82.2@3825,845 ; v1(3830,1200) C77.2@3875,1200 ; v2(3900,900) R100.2@3930.5,900 ; v2(3900,975) C80.2@3930.5,975 ; v1(3900,1125) C78.2@3930.5,1125 ; v2(3995,1400) 3995.47,1400.47 LD5.1@3995.47,1465.94 ; v1(4006.81,1086.81) U16.8@4075,1086.81
  TopLayer w25: v3(1325,1400) L2.1@1397.5,1400
  BottomLayer w8: v2(1845,2220) v2(2390,2220) 2390.55,2219.45 2569.45,2219.45 ; 2172.64,4442.36 v1(2172.64,4517.64)
  other v1: 675,-247.5 2000,-247.5 3352.5,-247.5 200,-200 250,-200 620,-200 670,-200 1000,-200 1050,-200 1400,-200 1450,-200 1980,-200 2030,-200 200,-150 250,-150 620,-150 670,-150 1000,-150 1050,-150 1400,-150 1450,-150 1980,-150 2030,-150 3055,10 3640,150 3690,150 4050,150 4100,150 3050,180 1000,195 1055,195 550,200 600,200 3640,200 3690,200 4050,200 4100,200 2227.5,245 2277.5,245 550,250 600,250 1000,250 1050,250 2227.5,295 2277.5,295 1075,350 1150,350 1660,350 1710,350 2680,360 2730,360 3060,360 3110,360 1660,400 1710,400 2680,410 2730,410 3060,410 3110,410 1075,425 1150,425 3300,430 3350,430 3300,480 3350,480 2675,525 3094.5,540 360,590 410,590 360,640 410,640 810,650 860,650 1550,700 810,705 860,705 1800,745 1550,750 1675,750 1900,750 2650,925 1675,975 1625,980 2440,990 2490,990 1625,1025 1675,1025 2440,1040 2490,1040 3075,1125 3200,1250 2400,1300 2475,1300 1225,1350 1825,1350 2966.42,1366.42 2400,1375 2475,1375 1550,1540 1700,1820 1855,1820 2980,2300 2525,2350 2750,2350 2980,2400 2280,2565 2330,2565 2280,2615 2330,2615 2520,2645 2570,2645 2520,2695 2570,2695 1620,2790 1670,2790 1620,2840 1670,2840 1620,2915 2925,2930 2975,2930 -120,2950 -70,2950 1925,2950 2125,2950 2925,2980 2975,2980 -120,3000 -70,3000 1625,3025 1625,3125 1980,3140 2100,3140 1300,3500 1300,3650 2522.87,3662.13 2525,3931.1 840,4080 2515,4127.95 2515.2,4324.8 3920,4670 3970,4670 3920,4720 3970,4720 845,4800 3920,4930 3970,4930 3920,4980 3970,4980 2950,5250 1320,5315 550,6100 900,6225 950,6225 180,6270 230,6270 900,6275 950,6275 180,6320 230,6320 3600,6370 3650,6370 4000,6370 4050,6370 3600,6420 3650,6420 4000,6420 4050,6420
  other v2: 2830.5,1100
HDMI_+5V: C15.1 CN2.18 CN3.18 R13.1 R14.1 R26.1 SB1.2 | length 3349.1
  TopLayer w5: v1(2572.5,5107.5) R26.1@2572.5,5150 ; R13.1@2725,5469.5 v1(2725,5500) ; R14.1@2800,5469.5 v1(2800,5500) ; SB1.2@2875,5463 SB1.2@2875,5468 ; SB1.2@2882,5468 v1(2919.5,5430.5) C15.1@2950,5430.5
  TopLayer w12: SB1.2@2875,5468 2875,5525 3275,5925 3450,5925 3500,5875 3500,5635 3642.48,5492.52 CN2.18@3800,5492.52 ; v1(3675,4695) 3677.48,4692.52 CN3.18@3800,4692.52
  VCC w20: v1(2572.5,5107.5) 2572.5,5372.5 2700,5500 2850,5500 v1(2919.5,5430.5)
  BottomLayer w12: v1(3650,5492.52) 3575,5417.52 3575,4900 3675,4800 v1(3675,4695)
HDMI_CEC: CN2.13 CN3.13 D1.2 U2.16 | length 2960.2
  TopLayer w5: U2.16@2731.1,5324.8 2731.1,5350 2645,5436.1 2645,5470 2720,5545 2820,5545 3250,5975 3475,5975 3550,5900 v1(3550,5675) 3634.06,5590.94 CN2.13@3800,5590.94 ; v1(3575,4825) 3609.06,4790.94 CN3.13@3800,4790.94
  BottomLayer w5: v1(3550,5675) 3575,5650 3575,5530.86 3545,5500.86 3545,4855 v1(3575,4825)
HDMI_HPD: CN2.19 CN3.19 U2.10 | length 2719.8
  TopLayer w5: U2.10@2849.21,5324.8 2849.21,5350 2874.21,5375 2955,5375 2975,5395 2975,5575 3292.51,5892.51 3437.49,5892.51 3470,5860 3470,5630 3627.17,5472.83 CN2.19@3800,5472.83 ; v1(3550,4775) 3652.17,4672.83 CN3.19@3800,4672.83
  BottomLayer w5: v1(3535,5565) 3535,5535 3515,5515 3515,4810 v1(3550,4775)
HDMI_SCL: CN2.15 CN3.15 R13.2 U2.14 | length 2942.1
  TopLayer w5: U2.14@2770.47,5324.8 2770.47,5354.53 2725,5400 R13.2@2725,5430.5 2714.5,5430.5 2700,5445 2700,5500 2735,5535 2825,5535 3255,5965 3470.86,5965 3530,5905.86 3530,5670 3648.43,5551.57 CN2.15@3800,5551.57 ; v1(3575,4800) 3623.43,4751.57 CN3.15@3800,4751.57
  BottomLayer w5: v1(3550.48,5649.52) 3565,5635 3565,5535 3535,5505 3535,4840 v1(3575,4800)
HDMI_SDA: CN2.16 CN3.16 R14.2 U2.13 | length 2894.3
  TopLayer w5: U2.13@2790.16,5324.8 2790.16,5390.16 2800,5400 R14.2@2800,5430.5 2784.5,5430.5 2775,5440 2775,5500 2800,5525 2829.14,5525 3259.14,5955 3465,5955 3520,5900 3520,5655 3643.11,5531.89 CN2.16@3800,5531.89 ; v1(3575,4775) 3618.11,4731.89 CN3.16@3800,4731.89
  BottomLayer w5: v1(3525.04,5649.96) 3555,5620 3555,5540 3525,5510 3525,4825 v1(3575,4775)
LED_STLINK: R89.2 R90.1 U14.30 | length 1383.2
  TopLayer w5: U14.30@2582.68,1334.84 2709.84,1334.84 v2(2800,1425) ; v2(3775,1500) R90.1@3897.5,1500
  BottomLayer w5: v2(2800,1425) 2850,1475 3750,1475 v2(3775,1500)
MCO: U14.29
NetB3_2: B3.2 B3.3 C86.2 R102.1 R103.1 | length 1401.5
  TopLayer w5: B3.2@1822.83,-72.5 B3.3@2177.17,-72.5 ; B3.2@1825,-70.33 1825,0 1925,100 1925,660 1935,670 C86.2@1940,670 ; R102.1@1850,830.5 1894.5,830.5 1902.5,822.5 R103.1@1950,822.5 C86.2@1950,669.5
NetB4_2: B4.2 B4.3 C87.2 R109.1 R122.1 | length 1722
  TopLayer w5: R109.1@2450,822.5 C87.2@2450,669.5 2570.5,669.5 2600,640 2600,325 2997.5,-72.5 B4.3@3527.17,-72.5
NetC3_2: C3.2 JP2.2 | length 105.5
  TopLayer w5: C3.2@1625,5694.5 JP2.2@1625,5800
NetC14_2: C14.2 R17.2 U4.A2 | length 254.9
  TopLayer w5: R17.2@1570,5374.5 R17.2@1569.5,5375 ; U4.A2@1577.76,5185.24 1577.76,5341.74 1569.5,5350 R17.2@1569.5,5375 ; C14.2@1630.5,5375 R17.2@1569.5,5375
NetC24_2: C24.2 U5.2 | length 192
  TopLayer w5: C24.2@925,4519.5 925,4625 935,4635 970,4635 975.59,4629.41 U5.2@975.59,4600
